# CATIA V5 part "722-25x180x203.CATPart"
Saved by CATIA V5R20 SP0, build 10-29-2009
Part number: 722-25x180x203
Definition: NONE
Nomenclature: 722-25x180x203
Source: Unknown
Description: 722-25x180x203
Bounding box of the stored display mesh (mm): x -12.5 to 12.5, y -12.5 to 12.5, z -168 to 35
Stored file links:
  C:\Users\Utente\Desktop\IO LAVORO\3D X SITO CF\X SITO\722\722-25x180x203.CATPart
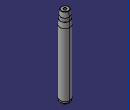
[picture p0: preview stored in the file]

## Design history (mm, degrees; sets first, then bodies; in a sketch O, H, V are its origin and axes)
Body1 "722-25x180x203" (main body)
  Solid1: solid without history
